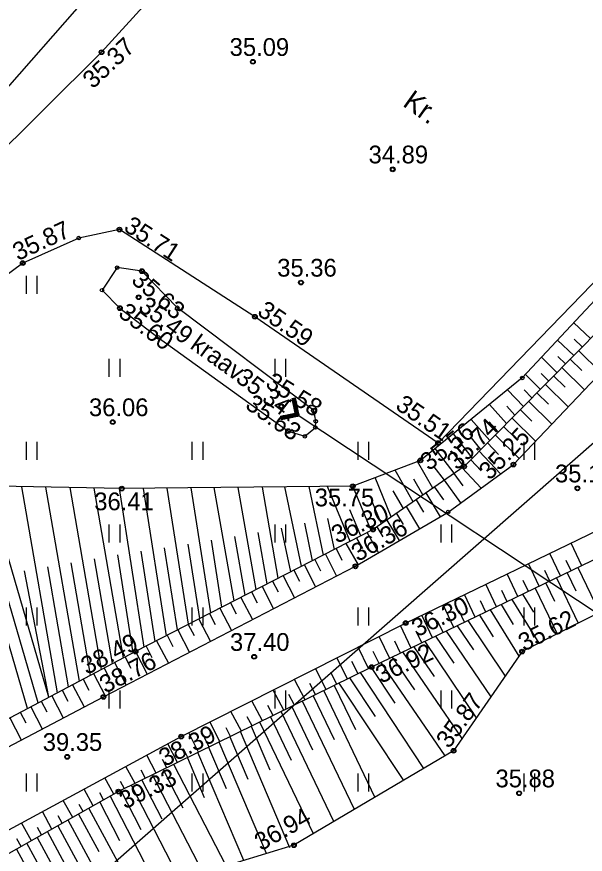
# Model space of a CAD drawing. Extents: x 641898 to 642452, y 6471715 to 6472255.
# Drawn here: x 642014.33 to 642038.32, y 6472114.87 to 6472150.22 of the extents above; entities that cross this region are included whole.
import ezdxf

# ---------------------------------------------------------------- set-up
doc = ezdxf.new("R2010")
doc.units = 0
for name, color, linetype in [('HALJASTUS', 7, 'Continuous'), ('KORGUS-EH2000', 7, 'Continuous'), ('MOOTMPUNKT', 7, 'Continuous'), ('PIIR', 7, 'Continuous'), ('RELJEEF', 7, 'Continuous'), ('TEE', 7, 'Continuous'), ('TRUUP', 7, 'Continuous'), ('VEEKOGU', 7, 'Continuous')]:
    doc.layers.add(name, color=color, linetype=linetype)

msp = doc.modelspace()

# ---------------------------------------------------------------- linework, layer by layer
at = {"layer": 'HALJASTUS'}
for p, q in [((642014.725, 6472139.282), (642014.725, 6472138.521)), ((642015.18, 6472139.282), (642015.18, 6472138.521)), ((642018.225, 6472135.782), (642018.225, 6472135.021)), ((642018.68, 6472135.782), (642018.68, 6472135.021)), ((642025.225, 6472135.782), (642025.225, 6472135.021)), ((642025.68, 6472135.782), (642025.68, 6472135.021)), ((642014.725, 6472132.282), (642014.725, 6472131.521)), ((642015.18, 6472132.282), (642015.18, 6472131.521)), ((642021.725, 6472132.282), (642021.725, 6472131.521)), ((642022.18, 6472132.282), (642022.18, 6472131.521)), ((642028.725, 6472132.282), (642028.725, 6472131.521)), ((642029.18, 6472132.282), (642029.18, 6472131.521)), ((642035.725, 6472132.282), (642035.725, 6472131.521)), ((642036.18, 6472132.282), (642036.18, 6472131.521)), ((642018.225, 6472128.782), (642018.225, 6472128.021)), ((642018.68, 6472128.782), (642018.68, 6472128.021)), ((642025.225, 6472128.782), (642025.225, 6472128.021)), ((642025.68, 6472128.782), (642025.68, 6472128.021)), ((642032.225, 6472128.782), (642032.225, 6472128.021)), ((642032.68, 6472128.782), (642032.68, 6472128.021)), ((642014.725, 6472125.282), (642014.725, 6472124.521)), ((642015.18, 6472125.282), (642015.18, 6472124.521)), ((642021.725, 6472125.282), (642021.725, 6472124.521)), ((642022.18, 6472125.282), (642022.18, 6472124.521)), ((642028.725, 6472125.282), (642028.725, 6472124.521)), ((642029.18, 6472125.282), (642029.18, 6472124.521)), ((642035.725, 6472125.282), (642035.725, 6472124.521)), ((642036.18, 6472125.282), (642036.18, 6472124.521)), ((642018.225, 6472121.782), (642018.225, 6472121.021)), ((642018.68, 6472121.782), (642018.68, 6472121.021)), ((642025.225, 6472121.782), (642025.225, 6472121.021)), ((642025.68, 6472121.782), (642025.68, 6472121.021)), ((642032.225, 6472121.782), (642032.225, 6472121.021)), ((642032.68, 6472121.782), (642032.68, 6472121.021)), ((642014.725, 6472118.282), (642014.725, 6472117.521)), ((642015.18, 6472118.282), (642015.18, 6472117.521)), ((642021.725, 6472118.282), (642021.725, 6472117.521)), ((642022.18, 6472118.282), (642022.18, 6472117.521)), ((642028.725, 6472118.282), (642028.725, 6472117.521)), ((642029.18, 6472118.282), (642029.18, 6472117.521)), ((642035.725, 6472118.282), (642035.725, 6472117.521)), ((642036.18, 6472118.282), (642036.18, 6472117.521))]:
    msp.add_line(p, q, dxfattribs=at)
at = {"layer": 'KORGUS-EH2000'}
for centre in [(642017.912, 6472148.72), (642024.297, 6472148.316), (642030.197, 6472143.778), (642018.666, 6472141.235), (642014.585, 6472139.818), (642019.613, 6472139.48), (642026.326, 6472138.999), (642019.476, 6472138.378), (642018.684, 6472137.917), (642024.382, 6472137.555), (642025.499, 6472133.776), (642026.872, 6472133.597), (642018.383, 6472133.109), (642025.785, 6472132.727), (642032.112, 6472132.22), (642031.363, 6472131.489), (642035.29, 6472131.318), (642033.209, 6472131.238), (642018.766, 6472130.302), (642028.508, 6472130.403), (642037.99, 6472130.314), (642029.368, 6472128.57), (642028.623, 6472127.021), (642030.743, 6472124.628), (642019.347, 6472123.425), (642024.351, 6472123.202), (642035.655, 6472123.419), (642029.307, 6472122.768), (642017.993, 6472121.511), (642021.273, 6472119.831), (642016.463, 6472118.98), (642032.765, 6472119.235), (642018.627, 6472117.511), (642035.531, 6472117.442), (642026.028, 6472115.246)]:
    msp.add_circle(centre, 0.1, dxfattribs=at)
at = {"layer": 'MOOTMPUNKT'}
for centre in [(642017.912, 6472148.72), (642024.297, 6472148.316), (642030.197, 6472143.778), (642018.666, 6472141.235), (642016.949, 6472140.875), (642014.585, 6472139.818), (642018.571, 6472139.63), (642019.613, 6472139.48), (642026.326, 6472138.999), (642017.933, 6472138.677), (642019.476, 6472138.378), (642018.684, 6472137.917), (642021.111, 6472137.935), (642024.382, 6472137.555), (642020.305, 6472136.686), (642035.664, 6472134.973), (642025.499, 6472133.776), (642026.163, 6472133.431), (642026.872, 6472133.597), (642018.383, 6472133.109), (642026.95, 6472133.144), (642025.785, 6472132.727), (642026.933, 6472132.879), (642026.49, 6472132.51), (642032.112, 6472132.22), (642031.363, 6472131.489), (642035.29, 6472131.318), (642033.209, 6472131.238), (642018.766, 6472130.302), (642028.508, 6472130.403), (642037.99, 6472130.314), (642032.534, 6472129.313), (642029.368, 6472128.57), (642028.623, 6472127.021), (642030.743, 6472124.628), (642019.347, 6472123.425), (642024.351, 6472123.202), (642035.655, 6472123.419), (642029.307, 6472122.768), (642017.993, 6472121.511), (642021.273, 6472119.831), (642016.463, 6472118.98), (642032.765, 6472119.235), (642018.627, 6472117.511), (642035.531, 6472117.442), (642026.028, 6472115.246)]:
    msp.add_circle(centre, 0.075, dxfattribs=at)
at = {"layer": 'PIIR'}
for p, q in [((642094.72, 6472181.39), (642016.19, 6472112.51)), ((642028, 6472163.22), (641981.64, 6472110.54))]:
    msp.add_line(p, q, dxfattribs=at)
at = {"layer": 'RELJEEF'}
for p, q in [((642038.541, 6472136.635), (642037.838, 6472137.3)), ((642037.838, 6472135.923), (642037.155, 6472136.569)), ((642038.19, 6472136.279), (642037.846, 6472136.604)), ((642038.038, 6472136.126), (642038.982, 6472135.2)), ((642037.127, 6472135.204), (642036.481, 6472135.847)), ((642037.487, 6472135.568), (642037.16, 6472135.877)), ((642037.687, 6472135.771), (642038.174, 6472135.292)), ((642037.336, 6472135.415), (642038.292, 6472134.475)), ((642036.424, 6472134.492), (642035.798, 6472135.116)), ((642036.776, 6472134.848), (642036.458, 6472135.164)), ((642036.984, 6472135.059), (642037.473, 6472134.579)), ((642036.633, 6472134.704), (642037.603, 6472133.75)), ((642035.714, 6472133.773), (642035.045, 6472134.471)), ((642036.065, 6472134.129), (642035.744, 6472134.464)), ((642036.282, 6472134.348), (642036.772, 6472133.866)), ((642035.93, 6472133.992), (642036.914, 6472133.026)), ((642034.997, 6472133.048), (642034.281, 6472133.853)), ((642035.349, 6472133.404), (642035.017, 6472133.778)), ((642035.58, 6472133.637), (642036.07, 6472133.153)), ((642034.293, 6472132.335), (642033.503, 6472133.223)), ((642035.228, 6472133.282), (642036.223, 6472132.3)), ((642034.645, 6472132.692), (642034.27, 6472133.113)), ((642034.877, 6472132.926), (642035.368, 6472132.441)), ((642033.556, 6472131.589), (642032.758, 6472132.619)), ((642033.91, 6472131.948), (642033.523, 6472132.448)), ((642034.525, 6472132.57), (642035.534, 6472131.575)), ((642034.193, 6472132.234), (642034.655, 6472131.741)), ((642032.789, 6472130.946), (642031.981, 6472131.99)), ((642033.2, 6472131.232), (642032.733, 6472131.836)), ((642033.841, 6472131.878), (642034.74, 6472130.918)), ((642031.885, 6472130.319), (642031.242, 6472131.443)), ((642033.49, 6472131.522), (642033.925, 6472131.058)), ((642031.061, 6472129.746), (642030.296, 6472131.083)), ((642032.378, 6472130.661), (642031.942, 6472131.223)), ((642033.125, 6472131.18), (642033.925, 6472130.325)), ((642030.138, 6472129.105), (642029.455, 6472130.763)), ((642031.473, 6472130.032), (642031.089, 6472130.704)), ((642032.78, 6472130.94), (642033.156, 6472130.421)), ((642014.784, 6472121.018), (642012.045, 6472130.428)), ((642015.687, 6472121.494), (642013.093, 6472130.409)), ((642016.05, 6472121.686), (642014.547, 6472130.381)), ((642016.98, 6472122.176), (642015.565, 6472130.362)), ((642017.91, 6472122.667), (642016.584, 6472130.343)), ((642018.84, 6472123.158), (642017.602, 6472130.324)), ((642022.524, 6472125.056), (642021.695, 6472130.332)), ((642023.502, 6472125.558), (642022.669, 6472130.342)), ((642024.434, 6472126.037), (642023.682, 6472130.353)), ((642025.366, 6472126.515), (642024.696, 6472130.363)), ((642026.353, 6472127.022), (642025.65, 6472130.373)), ((642027.276, 6472127.496), (642026.67, 6472130.384)), ((642028.4, 6472128.073), (642027.445, 6472130.392)), ((642029.292, 6472128.531), (642028.52, 6472130.408)), ((642031.958, 6472130.369), (642032.346, 6472129.834)), ((642032.369, 6472130.655), (642033.063, 6472129.698)), ((642019.71, 6472123.611), (642018.666, 6472130.304)), ((642020.647, 6472124.092), (642019.677, 6472130.311)), ((642021.587, 6472124.575), (642020.684, 6472130.322)), ((642030.649, 6472129.46), (642030.221, 6472130.208)), ((642031.593, 6472130.116), (642032.196, 6472129.115)), ((642029.717, 6472128.813), (642029.319, 6472129.781)), ((642031.182, 6472129.83), (642031.494, 6472129.311)), ((642028.846, 6472128.302), (642028.394, 6472129.4)), ((642030.77, 6472129.544), (642031.333, 6472128.609)), ((642027.737, 6472127.733), (642027.461, 6472129.045)), ((642029.944, 6472128.97), (642030.473, 6472128.105)), ((642030.356, 6472129.256), (642030.639, 6472128.793)), ((642025.892, 6472126.785), (642025.504, 6472128.635)), ((642026.814, 6472127.259), (642026.483, 6472128.84)), ((642029.533, 6472128.685), (642029.786, 6472128.271)), ((642023.968, 6472125.798), (642023.535, 6472128.284)), ((642024.9, 6472126.276), (642024.52, 6472128.455)), ((642028.671, 6472128.212), (642028.92, 6472127.771)), ((642029.116, 6472128.44), (642029.596, 6472127.591)), ((642022.056, 6472124.816), (642021.561, 6472127.963)), ((642022.992, 6472125.297), (642022.549, 6472128.119)), ((642028.225, 6472127.983), (642028.734, 6472127.086)), ((642038.177, 6472127.048), (642037.724, 6472128.002)), ((642019.241, 6472123.369), (642018.597, 6472127.5)), ((642020.178, 6472123.852), (642019.585, 6472127.654)), ((642021.115, 6472124.333), (642020.573, 6472127.808)), ((642027.36, 6472127.539), (642027.826, 6472126.608)), ((642027.805, 6472127.767), (642028.046, 6472127.285)), ((642037.275, 6472126.613), (642036.826, 6472127.568)), ((642017.445, 6472122.422), (642016.625, 6472127.165)), ((642018.375, 6472122.912), (642017.611, 6472127.336)), ((642026.915, 6472127.311), (642027.153, 6472126.837)), ((642037.725, 6472126.83), (642037.518, 6472127.271)), ((642015.687, 6472121.494), (642014.655, 6472126.825)), ((642016.515, 6472121.931), (642015.64, 6472126.995)), ((642026.025, 6472126.854), (642026.259, 6472126.389)), ((642026.47, 6472127.082), (642026.938, 6472126.148)), ((642036.374, 6472126.178), (642035.926, 6472127.133)), ((642036.824, 6472126.396), (642036.613, 6472126.847)), ((642038.005, 6472126.965), (642038.919, 6472125.069)), ((642015.236, 6472121.256), (642013.688, 6472126.574)), ((642025.581, 6472126.625), (642026.051, 6472125.688)), ((642035.473, 6472125.744), (642035.025, 6472126.698)), ((642037.104, 6472126.531), (642038.026, 6472124.618)), ((642037.555, 6472126.748), (642037.922, 6472125.986)), ((642024.685, 6472126.166), (642025.169, 6472125.231)), ((642025.13, 6472126.394), (642025.365, 6472125.941)), ((642034.574, 6472125.31), (642034.124, 6472126.262)), ((642035.924, 6472125.961), (642035.707, 6472126.422)), ((642036.204, 6472126.096), (642037.134, 6472124.167)), ((642036.654, 6472126.313), (642037.021, 6472125.552)), ((642024.24, 6472125.937), (642024.477, 6472125.481)), ((642033.673, 6472124.875), (642033.223, 6472125.827)), ((642035.024, 6472125.527), (642034.802, 6472125.996)), ((642035.673, 6472125.84), (642036.136, 6472125.089)), ((642023.35, 6472125.48), (642023.589, 6472125.021)), ((642023.795, 6472125.709), (642024.281, 6472124.77)), ((642032.772, 6472124.44), (642032.323, 6472125.392)), ((642034.123, 6472125.092), (642033.898, 6472125.569)), ((642034.768, 6472125.403), (642035.284, 6472124.565)), ((642035.221, 6472125.622), (642036.358, 6472123.775)), ((642022.461, 6472125.024), (642022.701, 6472124.561)), ((642022.906, 6472125.252), (642023.393, 6472124.31)), ((642033.223, 6472124.658), (642032.994, 6472125.142)), ((642034.315, 6472125.185), (642035.522, 6472123.226)), ((642022.016, 6472124.795), (642022.506, 6472123.85)), ((642031.872, 6472124.006), (642031.422, 6472124.956)), ((642032.322, 6472124.223), (642032.09, 6472124.715)), ((642033.367, 6472124.727), (642034.944, 6472122.389)), ((642033.863, 6472124.966), (642034.433, 6472124.041)), ((642021.126, 6472124.338), (642021.618, 6472123.39)), ((642021.571, 6472124.567), (642021.813, 6472124.1)), ((642030.972, 6472123.571), (642030.524, 6472124.517)), ((642032.912, 6472124.508), (642033.599, 6472123.489)), ((642020.681, 6472124.11), (642020.925, 6472123.64)), ((642030.071, 6472123.137), (642029.631, 6472124.065)), ((642031.422, 6472123.789), (642031.186, 6472124.287)), ((642032.002, 6472124.068), (642032.77, 6472122.929)), ((642032.457, 6472124.288), (642034.333, 6472121.506)), ((642019.791, 6472123.653), (642020.038, 6472123.179)), ((642020.237, 6472123.882), (642020.73, 6472122.93)), ((642029.171, 6472122.701), (642028.739, 6472123.613)), ((642030.521, 6472123.354), (642030.282, 6472123.859)), ((642031.082, 6472123.624), (642031.942, 6472122.368)), ((642031.547, 6472123.849), (642033.723, 6472120.622)), ((642019.347, 6472123.425), (642019.843, 6472122.47)), ((642029.621, 6472122.919), (642029.378, 6472123.432)), ((642033.125, 6472119.757), (642030.62, 6472123.414)), ((642018.462, 6472122.958), (642018.955, 6472122.01)), ((642018.904, 6472123.191), (642019.15, 6472122.718)), ((642028.292, 6472122.268), (642027.833, 6472123.154)), ((642028.74, 6472122.489), (642028.477, 6472122.998)), ((642032.413, 6472119.027), (642029.713, 6472122.968)), ((642030.171, 6472123.185), (642031.117, 6472121.803)), ((642018.02, 6472122.725), (642018.263, 6472122.257)), ((642027.394, 6472121.826), (642026.941, 6472122.702)), ((642029.285, 6472122.757), (642030.291, 6472121.24)), ((642017.135, 6472122.258), (642017.376, 6472121.796)), ((642017.578, 6472122.492), (642018.067, 6472121.549)), ((642026.497, 6472121.385), (642026.049, 6472122.25)), ((642027.843, 6472122.047), (642027.589, 6472122.539)), ((642028.38, 6472122.312), (642029.457, 6472120.688)), ((642031.512, 6472118.493), (642028.833, 6472122.535)), ((642016.693, 6472122.025), (642017.182, 6472121.085)), ((642026.945, 6472121.606), (642026.7, 6472122.08)), ((642027.733, 6472121.993), (642028.621, 6472120.14)), ((642027.928, 6472122.089), (642030.651, 6472117.983)), ((642015.809, 6472121.558), (642016.296, 6472120.621)), ((642016.251, 6472121.792), (642016.488, 6472121.335)), ((642025.606, 6472120.946), (642025.151, 6472121.795)), ((642026.055, 6472121.167), (642025.814, 6472121.617)), ((642026.836, 6472121.552), (642027.72, 6472119.708)), ((642027.284, 6472121.772), (642029.443, 6472117.268)), ((642015.366, 6472121.325), (642015.601, 6472120.874)), ((642024.709, 6472120.505), (642024.258, 6472121.343)), ((642025.158, 6472120.725), (642024.933, 6472121.144)), ((642028.579, 6472116.757), (642026.387, 6472121.331)), ((642014.482, 6472120.859), (642014.714, 6472120.413)), ((642014.924, 6472121.092), (642015.41, 6472120.156)), ((642023.811, 6472120.063), (642023.366, 6472120.891)), ((642027.716, 6472116.245), (642025.49, 6472120.889)), ((642025.939, 6472121.11), (642026.818, 6472119.275)), ((642014.04, 6472120.625), (642014.524, 6472119.691)), ((642022.9, 6472119.614), (642022.49, 6472120.448)), ((642024.26, 6472120.284), (642024.052, 6472120.671)), ((642026.852, 6472115.734), (642024.593, 6472120.447)), ((642025.041, 6472120.668), (642025.916, 6472118.843)), ((642023.349, 6472119.835), (642023.166, 6472120.207)), ((642024.228, 6472120.268), (642025.007, 6472118.426)), ((642022.003, 6472119.173), (642021.598, 6472119.996)), ((642022.452, 6472119.394), (642022.269, 6472119.765)), ((642023.329, 6472119.826), (642024.086, 6472118.036)), ((642025.854, 6472115.143), (642023.778, 6472120.047)), ((642021.111, 6472118.734), (642020.708, 6472119.526)), ((642022.43, 6472119.383), (642023.166, 6472117.647)), ((642024.874, 6472114.894), (642022.88, 6472119.604)), ((642020.213, 6472118.292), (642019.828, 6472119.051)), ((642021.559, 6472118.954), (642021.372, 6472119.323)), ((642023.912, 6472114.6), (642021.981, 6472119.162)), ((642020.662, 6472118.513), (642020.481, 6472118.869)), ((642023.165, 6472114.373), (642020.963, 6472118.661)), ((642021.532, 6472118.941), (642022.245, 6472117.257)), ((642019.328, 6472117.856), (642018.934, 6472118.568)), ((642019.765, 6472118.071), (642019.589, 6472118.416)), ((642020.514, 6472118.44), (642021.345, 6472116.822)), ((642018.436, 6472117.403), (642018.054, 6472118.093)), ((642019.617, 6472117.998), (642020.455, 6472116.366)), ((642022.193, 6472114.076), (642020.065, 6472118.219)), ((642017.565, 6472116.913), (642017.173, 6472117.617)), ((642018.879, 6472117.635), (642018.711, 6472117.937)), ((642019.168, 6472117.777), (642021.221, 6472113.78)), ((642018.001, 6472117.158), (642017.837, 6472117.453)), ((642018.281, 6472117.316), (642020.249, 6472113.483)), ((642018.719, 6472117.556), (642019.566, 6472115.909)), ((642016.694, 6472116.422), (642016.293, 6472117.142)), ((642017.13, 6472116.667), (642016.963, 6472116.967)), ((642017.845, 6472117.07), (642018.676, 6472115.452)), ((642015.821, 6472115.93), (642015.415, 6472116.668)), ((642016.935, 6472116.558), (642017.794, 6472114.98)), ((642017.371, 6472116.803), (642019.453, 6472112.979)), ((642014.95, 6472115.439), (642014.535, 6472116.193)), ((642016.257, 6472116.176), (642016.088, 6472116.482)), ((642018.643, 6472112.377), (642016.499, 6472116.312)), ((642015.385, 6472115.685), (642015.212, 6472116.001)), ((642016.064, 6472116.067), (642016.916, 6472114.502)), ((642014.514, 6472115.194), (642014.335, 6472115.519)), ((642015.192, 6472115.576), (642016.038, 6472114.023)), ((642017.832, 6472111.775), (642015.628, 6472115.821)), ((642017.022, 6472111.172), (642014.757, 6472115.33)), ((642014.321, 6472115.085), (642015.16, 6472113.545))]:
    msp.add_line(p, q, dxfattribs=at)
for points in [[(642006.634, 6472115.624), (642008.538, 6472116.55), (642017.993, 6472121.511), (642028.623, 6472127.021), (642032.534, 6472129.313), (642035.29, 6472131.318), (642042.314, 6472138.705), (642049.959, 6472146.539), (642050.735, 6472147.496), (642050.679, 6472148.514), (642050.124, 6472149.08), (642049.261, 6472148.828), (642043.691, 6472143.566), (642035.664, 6472134.973), (642031.363, 6472131.489), (642028.508, 6472130.403), (642018.766, 6472130.302), (642010.574, 6472130.456), (642006.315, 6472130.011), (642002.538, 6472126.116), (641998.265, 6472121.279), (641996.189, 6472118.754)], [(642049.525, 6472147.752), (642033.209, 6472131.238), (642029.368, 6472128.57), (642019.347, 6472123.425), (642009.733, 6472118.353), (642006.276, 6472116.303), (642004.319, 6472114.766), (642003.015, 6472112.887), (642001.569, 6472108.88), (641999.049, 6472106.763)], [(642009.422, 6472112.742), (642011.469, 6472114.538), (642021.273, 6472119.831), (642030.743, 6472124.628), (642039.752, 6472128.982), (642050.967, 6472134.85), (642058.208, 6472138.912), (642059.402, 6472139.059), (642060.171, 6472138.313), (642060.027, 6472137.169), (642058.959, 6472136.054), (642051.674, 6472131.646), (642042.143, 6472126.699), (642035.655, 6472123.419), (642032.765, 6472119.235), (642026.028, 6472115.246), (642020.049, 6472113.422), (642015.898, 6472110.337), (642013.512, 6472106.135), (642008.467, 6472103.33), (642003.93, 6472101.516)], [(642058.721, 6472137.77), (642054.392, 6472134.892), (642048.445, 6472131.824), (642038.57, 6472127.238), (642029.307, 6472122.768), (642018.627, 6472117.511), (642010.755, 6472113.076), (642008.847, 6472109.72), (642006.969, 6472107.208), (642003.529, 6472102.174)]]:
    msp.add_lwpolyline(points, dxfattribs=at)
at = {"layer": 'TEE'}
for points in [[(642037.166, 6472155.768), (642048.88, 6472149.179), (642039.451, 6472139.802), (642032.112, 6472132.22), (642024.382, 6472137.555), (642018.666, 6472141.235), (642016.949, 6472140.875), (642014.585, 6472139.818), (642012.337, 6472138.15), (642010.385, 6472136.585), (642007.19, 6472133.617), (642003.514, 6472129.77), (642000.657, 6472126.535), (641996.641, 6472121.738)], [(641994.664, 6472124.321), (641998.234, 6472128.673), (642008.103, 6472138.981), (642017.912, 6472148.72), (642020.695, 6472151.784)]]:
    msp.add_lwpolyline(points, dxfattribs=at)
at = {"layer": 'TRUUP'}
for p, q in [((642025.951, 6472134.109), (642026.091, 6472134.138)), ((642026.079, 6472133.486), (642025.951, 6472134.109)), ((642025.952, 6472134.104), (642026.106, 6472134.062)), ((642025.958, 6472134.077), (642026.112, 6472134.035)), ((642025.964, 6472134.049), (642026.118, 6472134.007)), ((642025.969, 6472134.022), (642026.123, 6472133.98)), ((642025.975, 6472133.994), (642026.129, 6472133.953)), ((642025.981, 6472133.967), (642026.134, 6472133.925)), ((642025.986, 6472133.939), (642026.14, 6472133.898)), ((642025.992, 6472133.912), (642026.146, 6472133.87)), ((642025.995, 6472134.118), (642026.101, 6472134.09)), ((642025.997, 6472133.885), (642026.151, 6472133.843)), ((642026.163, 6472133.431), (642026.021, 6472134.124)), ((642026.049, 6472134.13), (642026.095, 6472134.117)), ((642026.247, 6472133.376), (642026.091, 6472134.138)), ((642026.003, 6472133.857), (642026.157, 6472133.815)), ((642026.009, 6472133.83), (642026.163, 6472133.788)), ((642026.014, 6472133.802), (642026.168, 6472133.761)), ((642026.02, 6472133.775), (642026.174, 6472133.733)), ((642026.025, 6472133.747), (642026.179, 6472133.706)), ((642026.031, 6472133.72), (642026.185, 6472133.678)), ((642026.037, 6472133.693), (642026.191, 6472133.651)), ((642026.042, 6472133.665), (642026.196, 6472133.623)), ((642026.048, 6472133.638), (642026.202, 6472133.596)), ((642026.054, 6472133.61), (642026.207, 6472133.569)), ((642026.059, 6472133.583), (642026.213, 6472133.541)), ((642026.065, 6472133.555), (642026.219, 6472133.514)), ((642026.07, 6472133.528), (642026.224, 6472133.486)), ((642025.456, 6472133.359), (642026.079, 6472133.486)), ((642025.456, 6472133.359), (642025.485, 6472133.219)), ((642025.456, 6472133.358), (642025.759, 6472133.276)), ((642025.462, 6472133.33), (642025.705, 6472133.264)), ((642025.467, 6472133.303), (642025.651, 6472133.253)), ((642025.47, 6472133.289), (642026.163, 6472133.431)), ((642025.473, 6472133.276), (642025.596, 6472133.242)), ((642025.479, 6472133.248), (642025.542, 6472133.231)), ((642025.485, 6472133.219), (642026.247, 6472133.376)), ((642025.508, 6472133.37), (642025.814, 6472133.287)), ((642025.563, 6472133.381), (642025.868, 6472133.298)), ((642025.617, 6472133.392), (642025.923, 6472133.309)), ((642025.672, 6472133.403), (642025.977, 6472133.32)), ((642025.726, 6472133.414), (642026.032, 6472133.331)), ((642025.781, 6472133.425), (642026.086, 6472133.343)), ((642025.835, 6472133.436), (642026.14, 6472133.354)), ((642025.889, 6472133.448), (642026.195, 6472133.365)), ((642025.944, 6472133.459), (642026.247, 6472133.377)), ((642025.998, 6472133.47), (642026.241, 6472133.404)), ((642026.053, 6472133.481), (642026.236, 6472133.432)), ((642026.076, 6472133.501), (642026.23, 6472133.459))]:
    msp.add_line(p, q, dxfattribs=at)
msp.add_lwpolyline([(642026.163, 6472133.431), (642041.198, 6472123.463)], dxfattribs=at)
at = {"layer": 'VEEKOGU'}
msp.add_lwpolyline([(642026.95, 6472133.144), (642026.872, 6472133.597), (642021.111, 6472137.935), (642019.613, 6472139.48), (642018.571, 6472139.63), (642017.933, 6472138.677), (642018.684, 6472137.917), (642020.305, 6472136.686), (642025.785, 6472132.727), (642026.49, 6472132.51), (642026.933, 6472132.879), (642026.95, 6472133.144)], dxfattribs=at)

# ---------------------------------------------------------------- texts
at = {"layer": 'KORGUS-EH2000'}
for s, rotation, p in [('35.37', 43.2462, (642017.547, 6472147.144)), ('35.71', 327.081, (642018.801, 6472141.22)), ('35.87', 24.8375, (642014.382, 6472139.903)), ('35.63', 319.1115, (642019.123, 6472139.029)), ('35.60', 322.7467, (642018.572, 6472137.609)), ('35.49', 322.5181, (642019.411, 6472137.876)), ('35.59', 325.3731, (642024.438, 6472137.666)), ('35.34', 322.839, (642023.522, 6472134.856)), ('35.58', 328.3371, (642024.78, 6472134.617)), ('35.63', 324.8588, (642023.93, 6472133.724)), ('35.51', 325.2561, (642030.267, 6472133.698)), ('35.74', 44.7823, (642032.927, 6472131.044)), ('35.56', 38.084, (642031.727, 6472131.025)), ('35.25', 45.814, (642034.292, 6472130.62)), ('36.30', 25.1299, (642027.834, 6472127.968)), ('36.36', 29.7505, (642028.727, 6472127.196)), ('36.30', 25.339, (642031.223, 6472124.022)), ('35.62', 26.9039, (642035.737, 6472123.413)), ('38.49', 26.8602, (642017.287, 6472122.427)), ('36.92', 25.1851, (642029.705, 6472122.06)), ('38.76', 27.3414, (642018.075, 6472121.638)), ('35.87', 53.8919, (642032.572, 6472119.291)), ('38.39', 27.0744, (642020.574, 6472118.548)), ('39.33', 26.1669, (642018.899, 6472116.755)), ('36.94', 29.6752, (642024.639, 6472114.987))]:
    msp.add_text(s, height=0.75, rotation=rotation, dxfattribs=at).set_placement(p)
for s, p in [('35.09', (642023.317, 6472148.566)), ('34.89', (642029.179, 6472144.028)), ('35.36', (642025.324, 6472139.249)), ('36.06', (642017.381, 6472133.359)), ('35.14', (642037.044, 6472130.564)), ('36.41', (642017.604, 6472129.387)), ('35.75', (642026.907, 6472129.552)), ('37.40', (642023.331, 6472123.452)), ('39.35', (642015.43, 6472119.23)), ('35.88', (642034.533, 6472117.692))]:
    msp.add_text(s, height=0.75, dxfattribs=at).set_placement(p)
at = {"layer": 'TEE'}
msp.add_text('Kr.', height=0.85, rotation=324.5139, dxfattribs=at).set_placement((642030.575, 6472146.482))
at = {"layer": 'VEEKOGU'}
msp.add_text('kraav', height=0.75, rotation=324.3148, dxfattribs=at).set_placement((642021.606, 6472136.252))

doc.saveas('drawing.dxf')
